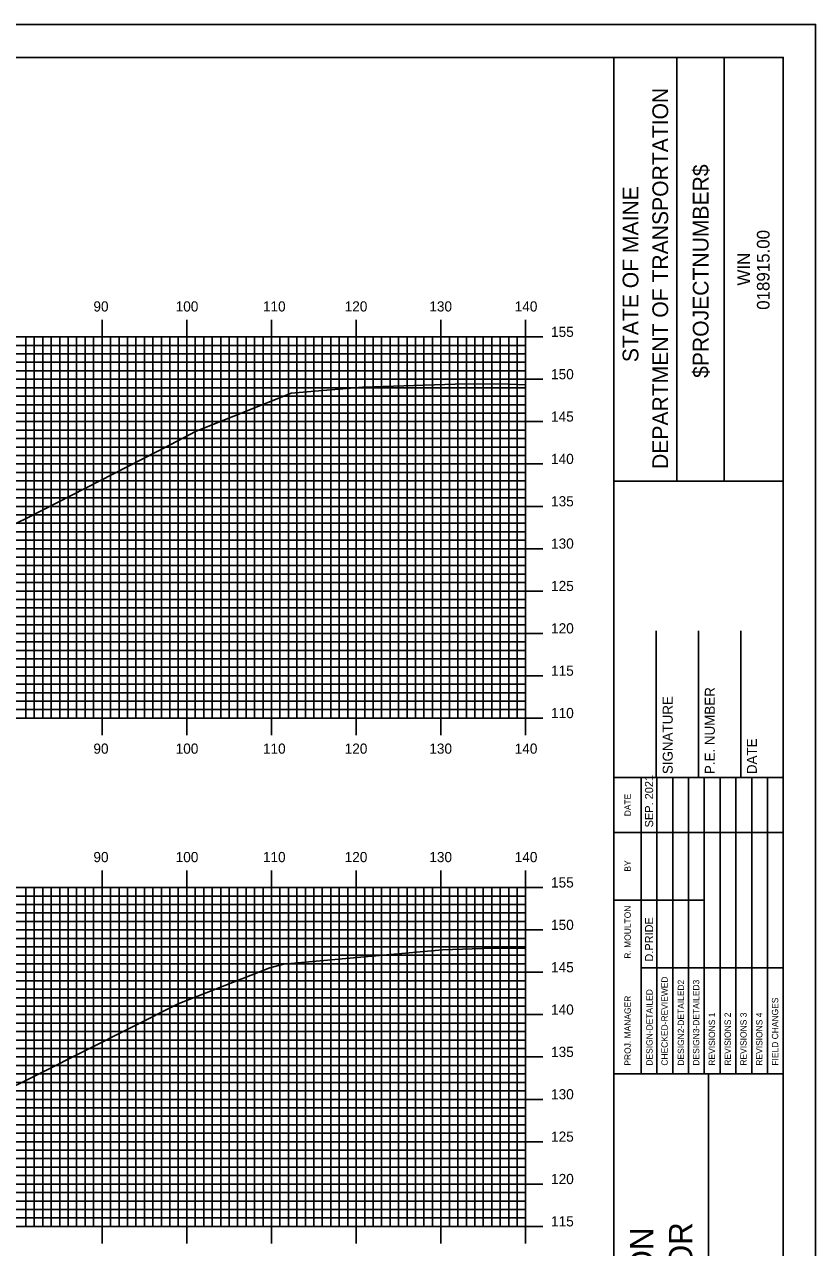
# Model space of a CAD drawing. Extents: x 854508 to 854851, y 364661 to 364881.
# Drawn here: x 854754.7 to 854848, y 364736.9 to 364881.3 of the extents above; entities that cross this region are included whole.
import ezdxf

# ---------------------------------------------------------------- set-up
doc = ezdxf.new("R2010")
doc.units = 0
for name, color, linetype in [('BORDER', 7, 'Continuous'), ('H_V ANNOTATION', 7, 'Continuous'), ('MAJOR', 7, 'Continuous'), ('MINOR', 7, 'Continuous'), ('PLOT BOUNDARY', 7, 'Continuous'), ('S_Roadway_Centerline', 7, 'Continuous')]:
    doc.layers.add(name, color=color, linetype=linetype)

msp = doc.modelspace()

# ---------------------------------------------------------------- linework, layer by layer
at = {"layer": 'BORDER'}
for p, q in [((854824.23, 364667.37), (854824.23, 364877.37)), ((854831.69, 364827.36), (854831.69, 364877.36)), ((854837.28, 364827.36), (854837.28, 364877.36)), ((854824.24, 364827.36), (854844.23, 364827.36)), ((854829.23, 364792.38), (854829.23, 364809.67)), ((854834.23, 364792.38), (854834.23, 364809.67)), ((854839.23, 364792.38), (854839.23, 364809.67)), ((854824.23, 364792.38), (854844.23, 364792.38)), ((854824.23, 364757.38), (854844.23, 364757.38)), ((854835.42, 364687.38), (854835.42, 364757.38))]:
    msp.add_line(p, q, dxfattribs=at)
msp.add_lwpolyline([(854524.23, 364667.37), (854844.23, 364667.37), (854844.23, 364877.37), (854524.23, 364877.37)], close=True, dxfattribs=at)
for points in [[(854827.46, 364785.88), (854827.46, 364792.38)], [(854829.33, 364757.38), (854829.33, 364792.38)], [(854831.19, 364792.38), (854831.19, 364757.38)], [(854833.06, 364757.38), (854833.06, 364792.38)], [(854834.92, 364757.38), (854834.92, 364792.38)], [(854836.78, 364757.38), (854836.78, 364792.38)], [(854838.65, 364757.38), (854838.65, 364792.38)], [(854840.51, 364757.38), (854840.51, 364792.38)], [(854842.37, 364757.38), (854842.37, 364792.38)], [(854827.47, 364757.38), (854827.47, 364790.96)], [(854824.23, 364785.88), (854844.23, 364785.88)], [(854824.23, 364777.88), (854827.47, 364777.88)], [(854827.46, 364777.88), (854834.92, 364777.88)], [(854827.46, 364769.88), (854844.23, 364769.88)]]:
    msp.add_lwpolyline(points, dxfattribs=at)
at = {"layer": 'MAJOR'}
for p, q in [((854763.83, 364846.37), (854763.83, 364844.37)), ((854773.83, 364846.37), (854773.83, 364844.37)), ((854783.83, 364846.37), (854783.83, 364844.37)), ((854793.83, 364846.37), (854793.83, 364844.37)), ((854803.83, 364846.37), (854803.83, 364844.37)), ((854813.83, 364846.37), (854813.83, 364844.37)), ((854533.83, 364844.37), (854813.83, 364844.37)), ((854533.83, 364844.37), (854813.83, 364844.37)), ((854763.83, 364799.37), (854763.83, 364844.37)), ((854773.83, 364799.37), (854773.83, 364844.37)), ((854783.83, 364799.37), (854783.83, 364844.37)), ((854793.83, 364799.37), (854793.83, 364844.37)), ((854803.83, 364799.37), (854803.83, 364844.37)), ((854815.84, 364844.37), (854811.83, 364844.37)), ((854813.83, 364799.37), (854813.83, 364844.37)), ((854813.83, 364799.37), (854813.83, 364844.37)), ((854533.83, 364839.37), (854813.83, 364839.37)), ((854815.84, 364839.37), (854811.83, 364839.37)), ((854533.83, 364834.37), (854813.83, 364834.37)), ((854815.84, 364834.37), (854811.83, 364834.37)), ((854533.83, 364829.37), (854813.83, 364829.37)), ((854815.84, 364829.37), (854811.83, 364829.37)), ((854533.83, 364824.37), (854813.83, 364824.37)), ((854815.84, 364824.37), (854811.83, 364824.37)), ((854533.83, 364819.37), (854813.83, 364819.37)), ((854815.84, 364819.37), (854811.83, 364819.37)), ((854533.83, 364814.37), (854813.83, 364814.37)), ((854815.84, 364814.37), (854811.83, 364814.37)), ((854533.83, 364809.37), (854813.83, 364809.37)), ((854815.84, 364809.37), (854811.83, 364809.37)), ((854533.83, 364804.37), (854813.83, 364804.37)), ((854815.84, 364804.37), (854811.83, 364804.37)), ((854533.83, 364799.37), (854813.83, 364799.37)), ((854533.83, 364799.37), (854813.83, 364799.37)), ((854763.83, 364797.37), (854763.83, 364799.37)), ((854773.83, 364797.37), (854773.83, 364799.37)), ((854783.83, 364797.37), (854783.83, 364799.37)), ((854793.83, 364797.37), (854793.83, 364799.37)), ((854803.83, 364797.37), (854803.83, 364799.37)), ((854815.84, 364799.37), (854811.83, 364799.37)), ((854813.83, 364797.37), (854813.83, 364799.37)), ((854763.83, 364781.37), (854763.83, 364779.37)), ((854773.83, 364781.37), (854773.83, 364779.37)), ((854783.83, 364781.37), (854783.83, 364779.37)), ((854793.83, 364781.37), (854793.83, 364779.37)), ((854803.83, 364781.37), (854803.83, 364779.37)), ((854813.83, 364781.37), (854813.83, 364779.37)), ((854533.83, 364779.37), (854813.83, 364779.37)), ((854533.83, 364779.37), (854813.83, 364779.37)), ((854763.83, 364739.37), (854763.83, 364779.37)), ((854773.83, 364739.37), (854773.83, 364779.37)), ((854783.83, 364739.37), (854783.83, 364779.37)), ((854793.83, 364739.37), (854793.83, 364779.37)), ((854803.83, 364739.37), (854803.83, 364779.37)), ((854815.84, 364779.37), (854811.83, 364779.37)), ((854813.83, 364739.37), (854813.83, 364779.37)), ((854813.83, 364739.37), (854813.83, 364779.37)), ((854533.83, 364774.37), (854813.83, 364774.37)), ((854815.84, 364774.37), (854811.83, 364774.37)), ((854533.83, 364769.37), (854813.83, 364769.37)), ((854815.84, 364769.37), (854811.83, 364769.37)), ((854533.83, 364764.37), (854813.83, 364764.37)), ((854815.84, 364764.37), (854811.83, 364764.37)), ((854533.83, 364759.37), (854813.83, 364759.37)), ((854815.84, 364759.37), (854811.83, 364759.37)), ((854533.83, 364754.37), (854813.83, 364754.37)), ((854815.84, 364754.37), (854811.83, 364754.37)), ((854533.83, 364749.37), (854813.83, 364749.37)), ((854815.84, 364749.37), (854811.83, 364749.37)), ((854533.83, 364744.37), (854813.83, 364744.37)), ((854815.84, 364744.37), (854811.83, 364744.37)), ((854533.83, 364739.37), (854813.83, 364739.37)), ((854533.83, 364739.37), (854813.83, 364739.37)), ((854763.83, 364737.37), (854763.83, 364739.37)), ((854773.83, 364737.37), (854773.83, 364739.37)), ((854783.83, 364737.37), (854783.83, 364739.37)), ((854793.83, 364737.37), (854793.83, 364739.37)), ((854803.83, 364737.37), (854803.83, 364739.37)), ((854815.84, 364739.37), (854811.83, 364739.37)), ((854813.83, 364737.37), (854813.83, 364739.37))]:
    msp.add_line(p, q, dxfattribs=at)
at = {"layer": 'MINOR'}
for p, q in [((854754.83, 364799.37), (854754.83, 364844.37)), ((854755.83, 364799.37), (854755.83, 364844.37)), ((854756.83, 364799.37), (854756.83, 364844.37)), ((854757.83, 364799.37), (854757.83, 364844.37)), ((854758.83, 364799.37), (854758.83, 364844.37)), ((854759.83, 364799.37), (854759.83, 364844.37)), ((854760.83, 364799.37), (854760.83, 364844.37)), ((854761.83, 364799.37), (854761.83, 364844.37)), ((854762.83, 364799.37), (854762.83, 364844.37)), ((854764.83, 364799.37), (854764.83, 364844.37)), ((854765.83, 364799.37), (854765.83, 364844.37)), ((854766.83, 364799.37), (854766.83, 364844.37)), ((854767.83, 364799.37), (854767.83, 364844.37)), ((854768.83, 364799.37), (854768.83, 364844.37)), ((854769.83, 364799.37), (854769.83, 364844.37)), ((854770.83, 364799.37), (854770.83, 364844.37)), ((854771.83, 364799.37), (854771.83, 364844.37)), ((854772.83, 364799.37), (854772.83, 364844.37)), ((854774.83, 364799.37), (854774.83, 364844.37)), ((854775.83, 364799.37), (854775.83, 364844.37)), ((854776.83, 364799.37), (854776.83, 364844.37)), ((854777.83, 364799.37), (854777.83, 364844.37)), ((854778.83, 364799.37), (854778.83, 364844.37)), ((854779.83, 364799.37), (854779.83, 364844.37)), ((854780.83, 364799.37), (854780.83, 364844.37)), ((854781.83, 364799.37), (854781.83, 364844.37)), ((854782.83, 364799.37), (854782.83, 364844.37)), ((854784.83, 364799.37), (854784.83, 364844.37)), ((854785.83, 364799.37), (854785.83, 364844.37)), ((854786.83, 364799.37), (854786.83, 364844.37)), ((854787.83, 364799.37), (854787.83, 364844.37)), ((854788.83, 364799.37), (854788.83, 364844.37)), ((854789.83, 364799.37), (854789.83, 364844.37)), ((854790.83, 364799.37), (854790.83, 364844.37)), ((854791.83, 364799.37), (854791.83, 364844.37)), ((854792.83, 364799.37), (854792.83, 364844.37)), ((854794.83, 364799.37), (854794.83, 364844.37)), ((854795.83, 364799.37), (854795.83, 364844.37)), ((854796.83, 364799.37), (854796.83, 364844.37)), ((854797.83, 364799.37), (854797.83, 364844.37)), ((854798.83, 364799.37), (854798.83, 364844.37)), ((854799.83, 364799.37), (854799.83, 364844.37)), ((854800.83, 364799.37), (854800.83, 364844.37)), ((854801.83, 364799.37), (854801.83, 364844.37)), ((854802.83, 364799.37), (854802.83, 364844.37)), ((854804.83, 364799.37), (854804.83, 364844.37)), ((854805.83, 364799.37), (854805.83, 364844.37)), ((854806.83, 364799.37), (854806.83, 364844.37)), ((854807.83, 364799.37), (854807.83, 364844.37)), ((854808.83, 364799.37), (854808.83, 364844.37)), ((854809.83, 364799.37), (854809.83, 364844.37)), ((854810.83, 364799.37), (854810.83, 364844.37)), ((854811.83, 364799.37), (854811.83, 364844.37)), ((854812.83, 364799.37), (854812.83, 364844.37)), ((854533.83, 364843.37), (854813.83, 364843.37)), ((854533.83, 364842.37), (854813.83, 364842.37)), ((854813.83, 364843.37), (854811.83, 364843.37)), ((854813.83, 364842.37), (854811.83, 364842.37)), ((854533.83, 364841.37), (854813.83, 364841.37)), ((854813.83, 364841.37), (854811.83, 364841.37)), ((854533.83, 364840.37), (854813.83, 364840.37)), ((854813.83, 364840.37), (854811.83, 364840.37)), ((854533.83, 364838.37), (854813.83, 364838.37)), ((854813.83, 364838.37), (854811.83, 364838.37)), ((854533.83, 364837.37), (854813.83, 364837.37)), ((854813.83, 364837.37), (854811.83, 364837.37)), ((854533.83, 364836.37), (854813.83, 364836.37)), ((854533.83, 364835.37), (854813.83, 364835.37)), ((854813.83, 364836.37), (854811.83, 364836.37)), ((854813.83, 364835.37), (854811.83, 364835.37)), ((854533.83, 364833.37), (854813.83, 364833.37)), ((854533.83, 364832.37), (854813.83, 364832.37)), ((854813.83, 364833.37), (854811.83, 364833.37)), ((854813.83, 364832.37), (854811.83, 364832.37)), ((854533.83, 364831.37), (854813.83, 364831.37)), ((854813.83, 364831.37), (854811.83, 364831.37)), ((854533.83, 364830.37), (854813.83, 364830.37)), ((854813.83, 364830.37), (854811.83, 364830.37)), ((854533.83, 364828.37), (854813.83, 364828.37)), ((854813.83, 364828.37), (854811.83, 364828.37)), ((854533.83, 364827.37), (854813.83, 364827.37)), ((854813.83, 364827.37), (854811.83, 364827.37)), ((854533.83, 364826.37), (854813.83, 364826.37)), ((854533.83, 364825.37), (854813.83, 364825.37)), ((854813.83, 364826.37), (854811.83, 364826.37)), ((854813.83, 364825.37), (854811.83, 364825.37)), ((854533.83, 364823.37), (854813.83, 364823.37)), ((854533.83, 364822.37), (854813.83, 364822.37)), ((854813.83, 364823.37), (854811.83, 364823.37)), ((854813.83, 364822.37), (854811.83, 364822.37)), ((854533.83, 364821.37), (854813.83, 364821.37)), ((854813.83, 364821.37), (854811.83, 364821.37)), ((854533.83, 364820.37), (854813.83, 364820.37)), ((854813.83, 364820.37), (854811.83, 364820.37)), ((854533.83, 364818.37), (854813.83, 364818.37)), ((854813.83, 364818.37), (854811.83, 364818.37)), ((854533.83, 364817.37), (854813.83, 364817.37)), ((854533.83, 364816.37), (854813.83, 364816.37)), ((854813.83, 364817.37), (854811.83, 364817.37)), ((854813.83, 364816.37), (854811.83, 364816.37)), ((854533.83, 364815.37), (854813.83, 364815.37)), ((854813.83, 364815.37), (854811.83, 364815.37)), ((854533.83, 364813.37), (854813.83, 364813.37)), ((854533.83, 364812.37), (854813.83, 364812.37)), ((854813.83, 364813.37), (854811.83, 364813.37)), ((854813.83, 364812.37), (854811.83, 364812.37)), ((854533.83, 364811.37), (854813.83, 364811.37)), ((854813.83, 364811.37), (854811.83, 364811.37)), ((854533.83, 364810.37), (854813.83, 364810.37)), ((854813.83, 364810.37), (854811.83, 364810.37)), ((854533.83, 364808.37), (854813.83, 364808.37)), ((854813.83, 364808.37), (854811.83, 364808.37)), ((854533.83, 364807.37), (854813.83, 364807.37)), ((854533.83, 364806.37), (854813.83, 364806.37)), ((854813.83, 364807.37), (854811.83, 364807.37)), ((854813.83, 364806.37), (854811.83, 364806.37)), ((854533.83, 364805.37), (854813.83, 364805.37)), ((854813.83, 364805.37), (854811.83, 364805.37)), ((854533.83, 364803.37), (854813.83, 364803.37)), ((854813.83, 364803.37), (854811.83, 364803.37)), ((854533.83, 364802.37), (854813.83, 364802.37)), ((854813.83, 364802.37), (854811.83, 364802.37)), ((854533.83, 364801.37), (854813.83, 364801.37)), ((854813.83, 364801.37), (854811.83, 364801.37)), ((854533.83, 364800.37), (854813.83, 364800.37)), ((854813.83, 364800.37), (854811.83, 364800.37)), ((854754.83, 364739.37), (854754.83, 364779.37)), ((854755.83, 364739.37), (854755.83, 364779.37)), ((854756.83, 364739.37), (854756.83, 364779.37)), ((854757.83, 364739.37), (854757.83, 364779.37)), ((854758.83, 364739.37), (854758.83, 364779.37)), ((854759.83, 364739.37), (854759.83, 364779.37)), ((854760.83, 364739.37), (854760.83, 364779.37)), ((854761.83, 364739.37), (854761.83, 364779.37)), ((854762.83, 364739.37), (854762.83, 364779.37)), ((854764.83, 364739.37), (854764.83, 364779.37)), ((854765.83, 364739.37), (854765.83, 364779.37)), ((854766.83, 364739.37), (854766.83, 364779.37)), ((854767.83, 364739.37), (854767.83, 364779.37)), ((854768.83, 364739.37), (854768.83, 364779.37)), ((854769.83, 364739.37), (854769.83, 364779.37)), ((854770.83, 364739.37), (854770.83, 364779.37)), ((854771.83, 364739.37), (854771.83, 364779.37)), ((854772.83, 364739.37), (854772.83, 364779.37)), ((854774.83, 364739.37), (854774.83, 364779.37)), ((854775.83, 364739.37), (854775.83, 364779.37)), ((854776.83, 364739.37), (854776.83, 364779.37)), ((854777.83, 364739.37), (854777.83, 364779.37)), ((854778.83, 364739.37), (854778.83, 364779.37)), ((854779.83, 364739.37), (854779.83, 364779.37)), ((854780.83, 364739.37), (854780.83, 364779.37)), ((854781.83, 364739.37), (854781.83, 364779.37)), ((854782.83, 364739.37), (854782.83, 364779.37)), ((854784.83, 364739.37), (854784.83, 364779.37)), ((854785.83, 364739.37), (854785.83, 364779.37)), ((854786.83, 364739.37), (854786.83, 364779.37)), ((854787.83, 364739.37), (854787.83, 364779.37)), ((854788.83, 364739.37), (854788.83, 364779.37)), ((854789.83, 364739.37), (854789.83, 364779.37)), ((854790.83, 364739.37), (854790.83, 364779.37)), ((854791.83, 364739.37), (854791.83, 364779.37)), ((854792.83, 364739.37), (854792.83, 364779.37)), ((854794.83, 364739.37), (854794.83, 364779.37)), ((854795.83, 364739.37), (854795.83, 364779.37)), ((854796.83, 364739.37), (854796.83, 364779.37)), ((854797.83, 364739.37), (854797.83, 364779.37)), ((854798.83, 364739.37), (854798.83, 364779.37)), ((854799.83, 364739.37), (854799.83, 364779.37)), ((854800.83, 364739.37), (854800.83, 364779.37)), ((854801.83, 364739.37), (854801.83, 364779.37)), ((854802.83, 364739.37), (854802.83, 364779.37)), ((854804.83, 364739.37), (854804.83, 364779.37)), ((854805.83, 364739.37), (854805.83, 364779.37)), ((854806.83, 364739.37), (854806.83, 364779.37)), ((854807.83, 364739.37), (854807.83, 364779.37)), ((854808.83, 364739.37), (854808.83, 364779.37)), ((854809.83, 364739.37), (854809.83, 364779.37)), ((854810.83, 364739.37), (854810.83, 364779.37)), ((854811.83, 364739.37), (854811.83, 364779.37)), ((854812.83, 364739.37), (854812.83, 364779.37)), ((854533.83, 364778.37), (854813.83, 364778.37)), ((854533.83, 364777.37), (854813.83, 364777.37)), ((854813.83, 364778.37), (854811.83, 364778.37)), ((854813.83, 364777.37), (854811.83, 364777.37)), ((854533.83, 364776.37), (854813.83, 364776.37)), ((854813.83, 364776.37), (854811.83, 364776.37)), ((854533.83, 364775.37), (854813.83, 364775.37)), ((854813.83, 364775.37), (854811.83, 364775.37)), ((854533.83, 364773.37), (854813.83, 364773.37)), ((854813.83, 364773.37), (854811.83, 364773.37)), ((854533.83, 364772.37), (854813.83, 364772.37)), ((854813.83, 364772.37), (854811.83, 364772.37)), ((854533.83, 364771.37), (854813.83, 364771.37)), ((854533.83, 364770.37), (854813.83, 364770.37)), ((854813.83, 364771.37), (854811.83, 364771.37)), ((854813.83, 364770.37), (854811.83, 364770.37)), ((854533.83, 364768.37), (854813.83, 364768.37)), ((854533.83, 364767.37), (854813.83, 364767.37)), ((854813.83, 364768.37), (854811.83, 364768.37)), ((854813.83, 364767.37), (854811.83, 364767.37)), ((854533.83, 364766.37), (854813.83, 364766.37)), ((854813.83, 364766.37), (854811.83, 364766.37)), ((854533.83, 364765.37), (854813.83, 364765.37)), ((854813.83, 364765.37), (854811.83, 364765.37)), ((854533.83, 364763.37), (854813.83, 364763.37)), ((854813.83, 364763.37), (854811.83, 364763.37)), ((854533.83, 364762.37), (854813.83, 364762.37)), ((854813.83, 364762.37), (854811.83, 364762.37)), ((854533.83, 364761.37), (854813.83, 364761.37)), ((854533.83, 364760.37), (854813.83, 364760.37)), ((854813.83, 364761.37), (854811.83, 364761.37)), ((854813.83, 364760.37), (854811.83, 364760.37)), ((854533.83, 364758.37), (854813.83, 364758.37)), ((854533.83, 364757.37), (854813.83, 364757.37)), ((854813.83, 364758.37), (854811.83, 364758.37)), ((854813.83, 364757.37), (854811.83, 364757.37)), ((854533.83, 364756.37), (854813.83, 364756.37)), ((854813.83, 364756.37), (854811.83, 364756.37)), ((854533.83, 364755.37), (854813.83, 364755.37)), ((854813.83, 364755.37), (854811.83, 364755.37)), ((854533.83, 364753.37), (854813.83, 364753.37)), ((854813.83, 364753.37), (854811.83, 364753.37)), ((854533.83, 364752.37), (854813.83, 364752.37)), ((854533.83, 364751.37), (854813.83, 364751.37)), ((854813.83, 364752.37), (854811.83, 364752.37)), ((854813.83, 364751.37), (854811.83, 364751.37)), ((854533.83, 364750.37), (854813.83, 364750.37)), ((854813.83, 364750.37), (854811.83, 364750.37)), ((854533.83, 364748.37), (854813.83, 364748.37)), ((854533.83, 364747.37), (854813.83, 364747.37)), ((854813.83, 364748.37), (854811.83, 364748.37)), ((854813.83, 364747.37), (854811.83, 364747.37)), ((854533.83, 364746.37), (854813.83, 364746.37)), ((854813.83, 364746.37), (854811.83, 364746.37)), ((854533.83, 364745.37), (854813.83, 364745.37)), ((854813.83, 364745.37), (854811.83, 364745.37)), ((854533.83, 364743.37), (854813.83, 364743.37)), ((854813.83, 364743.37), (854811.83, 364743.37)), ((854533.83, 364742.37), (854813.83, 364742.37)), ((854533.83, 364741.37), (854813.83, 364741.37)), ((854813.83, 364742.37), (854811.83, 364742.37)), ((854813.83, 364741.37), (854811.83, 364741.37)), ((854533.83, 364740.37), (854813.83, 364740.37)), ((854813.83, 364740.37), (854811.83, 364740.37))]:
    msp.add_line(p, q, dxfattribs=at)
at = {"layer": 'PLOT BOUNDARY'}
msp.add_lwpolyline([(854508.05, 364661.25), (854848.05, 364661.25), (854848.05, 364881.25), (854508.05, 364881.25)], close=True, dxfattribs=at)
at = {"layer": 'S_Roadway_Centerline'}
for points in [[(854741.19, 364816.27), (854755.18, 364823.11), (854771.94, 364831.67), (854774.84, 364833.21), (854786.16, 364837.72), (854794.57, 364838.45), (854805.5, 364838.8), (854810.74, 364838.82), (854813.83, 364838.73)], [(854751.06, 364754.74), (854756.47, 364757.44), (854772.82, 364765.65), (854783.65, 364769.91), (854785.24, 364770.31), (854787.8, 364770.57), (854804, 364772.03), (854809.89, 364772.2), (854813.83, 364772.18)]]:
    msp.add_lwpolyline(points, dxfattribs=at)

# ---------------------------------------------------------------- texts
at = {"layer": 'BORDER'}
for s, height, p in [('DEPARTMENT OF TRANSPORTATION', 1.8635, (854830.65, 364828.78)), ('$PROJECTNUMBER$', 1.8635, (854835.42, 364839.53)), ('STATE OF MAINE', 1.8635, (854827.14, 364841.39)), ('018915.00', 1.491, (854842.62, 364847.57)), ('WIN', 1.491, (854840.31, 364850.43)), ('SIGNATURE', 1.181, (854831.19, 364792.76)), ('P.E. NUMBER', 1.1811, (854836.16, 364792.76)), ('DATE', 1.181, (854841.12, 364792.76)), ('SEP. 2021', 0.969, (854828.88, 364786.47)), ('DATE', 0.743, (854826.24, 364787.79)), ('BY', 0.743, (854826.24, 364781.25)), ('R. MOULTON', 0.745, (854826.24, 364770.98)), ('D.PRIDE', 0.969, (854828.88, 364770.62)), ('CHECKED-REVIEWED', 0.7455, (854830.6, 364758.35)), ('DESIGN-DETAILED', 0.7455, (854828.81, 364758.35)), ('DESIGN2-DETAILED2', 0.7455, (854832.53, 364758.35)), ('DESIGN3-DETAILED3', 0.7455, (854834.32, 364758.35)), ('PROJ. MANAGER', 0.7455, (854826.24, 364758.35)), ('FIELD CHANGES', 0.7455, (854843.64, 364758.35)), ('REVISIONS 1', 0.7455, (854836.19, 364758.35)), ('REVISIONS 2', 0.7455, (854838.05, 364758.35)), ('REVISIONS 3', 0.7455, (854839.91, 364758.35)), ('REVISIONS 4', 0.7455, (854841.78, 364758.35)), ('BREWER TO EDDINGTON', 2.7557, (854828.91, 364693.78)), ('I-395/ROUTE 9 CONNECTOR', 2.7557, (854833.5, 364689.7))]:
    msp.add_text(s, height=height, rotation=90, dxfattribs=at).set_placement(p)
at = {"layer": 'H_V ANNOTATION'}
for s, p in [('90', (854762.81, 364847.37)), ('100', (854772.52, 364847.37)), ('110', (854782.82, 364847.37)), ('120', (854792.47, 364847.37)), ('130', (854802.46, 364847.37)), ('140', (854812.54, 364847.37)), ('155', (854816.83, 364844.37)), ('150', (854816.83, 364839.37)), ('145', (854816.83, 364834.37)), ('140', (854816.83, 364829.37)), ('135', (854816.83, 364824.37)), ('130', (854816.83, 364819.37)), ('125', (854816.83, 364814.37)), ('120', (854816.83, 364809.37)), ('115', (854816.83, 364804.37)), ('110', (854816.83, 364799.37)), ('90', (854762.81, 364795.17)), ('100', (854772.52, 364795.17)), ('110', (854782.82, 364795.17)), ('120', (854792.47, 364795.17)), ('130', (854802.46, 364795.17)), ('140', (854812.54, 364795.17)), ('90', (854762.81, 364782.37)), ('100', (854772.52, 364782.37)), ('110', (854782.82, 364782.37)), ('120', (854792.47, 364782.37)), ('130', (854802.46, 364782.37)), ('140', (854812.54, 364782.37)), ('155', (854816.83, 364779.37)), ('150', (854816.83, 364774.37)), ('145', (854816.83, 364769.37)), ('140', (854816.83, 364764.37)), ('135', (854816.83, 364759.37)), ('130', (854816.83, 364754.37)), ('125', (854816.83, 364749.37)), ('120', (854816.83, 364744.37)), ('115', (854816.83, 364739.37))]:
    msp.add_text(s, height=1.2, dxfattribs=at).set_placement(p)

doc.saveas('drawing.dxf')
